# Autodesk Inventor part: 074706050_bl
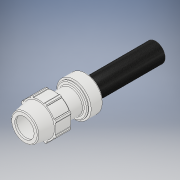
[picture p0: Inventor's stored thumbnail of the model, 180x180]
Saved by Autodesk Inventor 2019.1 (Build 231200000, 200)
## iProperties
Created: 2022-07
Part Number: 074706050_bl
Material: PVC-Piping
Description: Plasson Adjustable Elbow 50 x 50 mm
Document SubType Name: Modeling
Designer: comp2
Density: 1.4 g/cm^3
Appearance: Smooth - White
Author: comp2
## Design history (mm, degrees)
derived "07470.ipt"
feature "Solid1::07470.ipt" dims "ScaleForDerivedMember" = 10
feature "Solid2::07470.ipt" dims "ScaleForDerivedMember" = 10
feature "Solid3::07470.ipt" dims "ScaleForDerivedMember" = 10
feature "Solid4::07470.ipt" dims "ScaleForDerivedMember" = 10
tag "TaggingFeature1"
body "Solid1"
body "Solid2"
body "Solid3"
body "Solid4"
other parameters: "d6" = 96 [user parameter], "d7" = 41 [user parameter], "d9" = 45 deg [user parameter], "d10" = 25 [user parameter], "d11" = 173 [user parameter], "d12" = 55 [user parameter], "d13" = 216.25 [user parameter], "d14" = 86.5 [user parameter], "d15" = 1 [user parameter], "d16" = 31.14 [user parameter], "d17" = 72.5 [user parameter], "d19" = 82.5 [user parameter], "d20" = 8 deg [user parameter], "d21" = 34.3 [user parameter], "d22" = 5 [user parameter], "d24" = 8.375 [user parameter], "d25" = 1.7 [user parameter], "d26" = 1.7 [user parameter], "d27" = 85 deg [user parameter], "d28" = 98 [user parameter], "d30" = 39.2 [user parameter], "d31" = 2 [user parameter], "d32" = 42.5 [user parameter], "d33" = 3.92 [user parameter], "d38" = 89.28 [user parameter], "d39" = 35 deg [user parameter], "d40" = 17.5 deg [user parameter], "d42" = 0 [user parameter], "d43" = 1.92 [user parameter], "d47" = 360 deg [user parameter], "d49" = 2.5 [user parameter], "d50" = 8.82 [user parameter], "l1" = 173 [user parameter], "l_" = 98 [user parameter], "E_" = 96 [user parameter], "d23" = 8.375 [user parameter]
